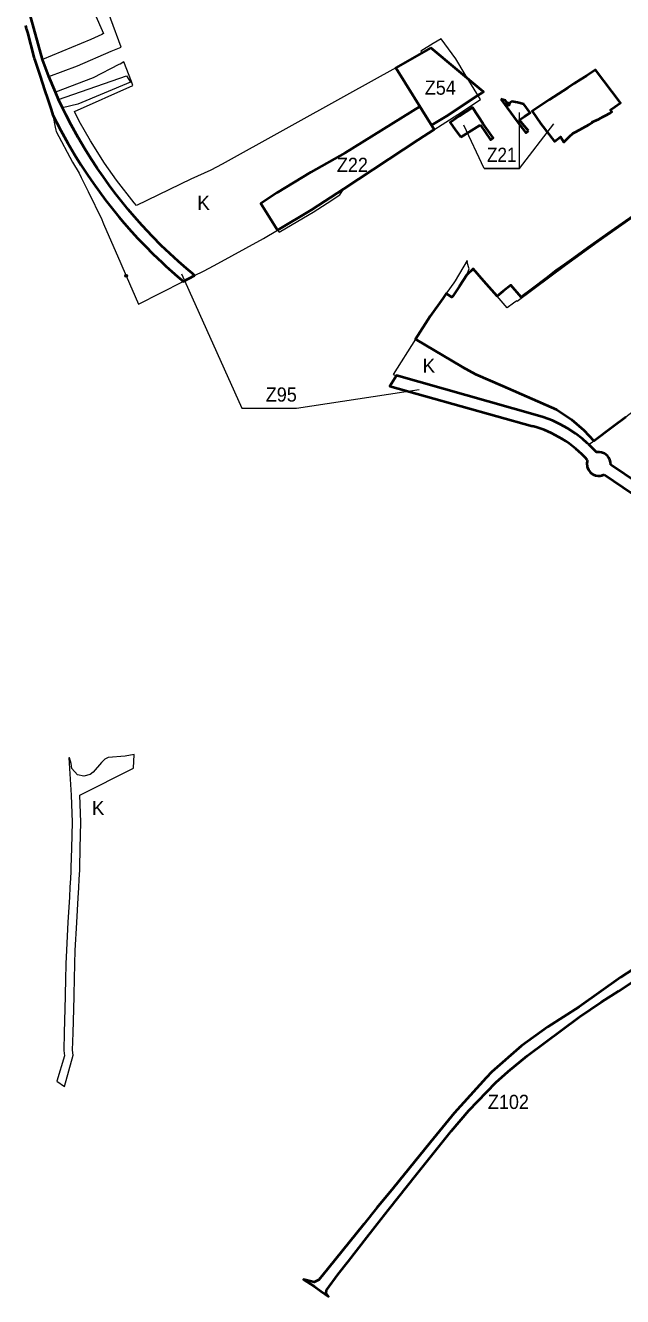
# Model space of a CAD drawing. Extents: x -650276 to -642489, y -1074311 to -1066658.
# Drawn here: x -649054 to -648043, y -1072846 to -1070697 of the extents above; entities that cross this region are included whole.
import ezdxf

# ---------------------------------------------------------------- set-up
doc = ezdxf.new("R2010")
doc.units = 0
doc.header["$LTSCALE"] = 9.6
doc.header["$PDMODE"] = 32
doc.header["$PDSIZE"] = 4.8
for name, color, linetype, lineweight in [('42', 7, 'Continuous', 25), ('44', 7, 'Continuous', 40), ('45', 7, 'Continuous', 40), ('46', 7, 'Continuous', 13), ('47', 7, 'Continuous', 13), ('48', 7, 'Continuous', 13), ('63', 7, 'Continuous', 13)]:
    doc.layers.add(name, color=color, linetype=linetype, lineweight=lineweight)

msp = doc.modelspace()

# ---------------------------------------------------------------- linework, layer by layer
at = {"layer": '42'}
msp.add_lwpolyline([(-648386.587, -1070833.807), (-648512.981, -1070911.776), (-648571.14, -1070944.67), (-648628.712, -1070979.892), (-648655.76, -1070997.5), (-648627.39, -1071042.65), (-648570.23, -1071008.2), (-648515.46, -1070972.94), (-648389.33, -1070889.79), (-648362.519, -1070872.788)], close=True, dxfattribs=at)
at = {"layer": '44'}
for points in [[(-649054.31, -1070696.44), (-649052.77, -1070702.25), (-649052.44, -1070703.48), (-649051.03, -1070708.74), (-649040.03, -1070750.06), (-649039.38, -1070752.51), (-649039.06, -1070753.72), (-649038.51, -1070755.38), (-649027.74, -1070787.51), (-649027.64, -1070787.8), (-649019.48, -1070812.18), (-649018.48, -1070815.18), (-649011.24, -1070836.79), (-649010.67, -1070838.5), (-649007.885, -1070848.153), (-648994.464, -1070873.974), (-648982.467, -1070895.704), (-648970.712, -1070915.663), (-648960.268, -1070932.429), (-648949.389, -1070949.031), (-648939.232, -1070963.818), (-648918.601, -1070991.969), (-648896.068, -1071020.184), (-648886.874, -1071031.044), (-648874.793, -1071044.773), (-648863.847, -1071056.723), (-648851.175, -1071069.886), (-648838.696, -1071082.562), (-648823.087, -1071097.562), (-648816.379, -1071103.782), (-648806.239, -1071112.938), (-648797, -1071121), (-648790.23, -1071126.818), (-648787.207, -1071129.363), (-648767.824, -1071119.455), (-648771.725, -1071116.233), (-648781.806, -1071107.721), (-648795.407, -1071095.8), (-648824.292, -1071068.677), (-648839.273, -1071053.556), (-648856.883, -1071034.761), (-648869.629, -1071020.411), (-648880.44, -1071007.703), (-648894.164, -1070990.806), (-648902.714, -1070979.812), (-648912.396, -1070966.893), (-648922.92, -1070952.242), (-648932.78, -1070937.887), (-648943.414, -1070921.659), (-648953.605, -1070905.299), (-648965.093, -1070885.794), (-648976.834, -1070864.527), (-648985.145, -1070848.538), (-648991.386, -1070835.954), (-648998.132, -1070821.723), (-649003.641, -1070809.566), (-649014.888, -1070782.994), (-649025.129, -1070754.377), (-649047.11, -1070674.743)], [(-648079.109, -1071418.563), (-648082.391, -1071418.063), (-648085.477, -1071418.086), (-648087.928, -1071418.446), (-648100.438, -1071405.517), (-648103.268, -1071402.88), (-648111.646, -1071395.618), (-648123.313, -1071386.696), (-648136.263, -1071378.194), (-648149.571, -1071370.788), (-648162.084, -1071364.918), (-648178.158, -1071358.781), (-648191.25, -1071354.858), (-648426.18, -1071288.32), (-648437.454, -1071306.778), (-648196.236, -1071374.226)], [(-648069.022, -1071424.443), (-648074.341, -1071420.189), (-648079.108, -1071418.564), (-648079.109, -1071418.563)], [(-648063.593, -1071439.723), (-648063.862, -1071435.078), (-648064.838, -1071431.28), (-648066.623, -1071427.592), (-648069.022, -1071424.443)], [(-648103.894, -1071436.836), (-648103.478, -1071442.736), (-648101.203, -1071448.31)], [(-648101.203, -1071448.31), (-648098.259, -1071452.196), (-648096.014, -1071454.192), (-648093.059, -1071456.066), (-648089.539, -1071457.489), (-648085.585, -1071458.248), (-648081.642, -1071458.215), (-648078.539, -1071457.636), (-648074.86, -1071456.248)], [(-648016.446, -1071471.268), (-648063.593, -1071439.723)], [(-648074.86, -1071456.248), (-648027.562, -1071487.894)], [(-647942.21, -1072238.54), (-648046.69, -1072306.3), (-648117.12, -1072356), (-648169.81, -1072390.035), (-648214.73, -1072422.41), (-648264.618, -1072466.244), (-648274.53, -1072476.196), (-648328.847, -1072535.816), (-648369.37, -1072585.645), (-648431.557, -1072662.77), (-648459.243, -1072696.417), (-648481.468, -1072723.736), (-648543.255, -1072800.016), (-648557.588, -1072817.727), (-648565.726, -1072822.048), (-648583.407, -1072817.256), (-648564.86, -1072829.45), (-648554.22, -1072836.89), (-648541.102, -1072846.281), (-648545.462, -1072840.329), (-648544.632, -1072835.177), (-648524.979, -1072808.383), (-648507.503, -1072786.605), (-648476.204, -1072746.1), (-648452.274, -1072715.637), (-648439.912, -1072699.826), (-648391.796, -1072639.344), (-648333.178, -1072565.837), (-648303.791, -1072531.792), (-648258.165, -1072484.283), (-648237.406, -1072465.811), (-648205.298, -1072439.308), (-648116.32, -1072373.44), (-648079.76, -1072348.46), (-648050.276, -1072330.025), (-647969.894, -1072276.479)]]:
    msp.add_lwpolyline(points, dxfattribs=at)
at = {"layer": '44', "lineweight": 13}
msp.add_lwpolyline([(-648790.074, -1071116.496), (-648687.825, -1071343.817), (-648595.588, -1071343.817), (-648387.63, -1071312.498)], dxfattribs=at)
at = {"layer": '44'}
for centre, radius, start, end in [((-648244.965, -1071557.871), 190, 41.59858, 75.1393), ((-648083.781, -1071438.172), 20.157, 161.35794, 176.20098)]:
    msp.add_arc(centre, radius, start, end, dxfattribs=at)
at = {"layer": '45'}
msp.add_lwpolyline([(-648368.163, -1070734.376), (-648427.25, -1070767.95), (-648366.98, -1070865.44), (-648341.58, -1070849.98), (-648287.74, -1070814.32), (-648282.44, -1070810.84), (-648278.832, -1070808.761)], close=True, dxfattribs=at)
for points in [[(-648095.42, -1070860.3), (-648083.65, -1070854.89), (-648076.73, -1070851.07), (-648074.41, -1070849.79), (-648072.59, -1070848.79), (-648065.35, -1070844.8), (-648061.52, -1070842.68), (-648063.76, -1070839.49), (-648056.61, -1070834.26), (-648047.17, -1070827.35), (-648089.27, -1070771.57), (-648104.78, -1070781.65), (-648114.77, -1070788.08), (-648125.2, -1070794.79), (-648136.08, -1070801.79)], [(-648095.42, -1070860.3), (-648083.65, -1070854.89), (-648076.73, -1070851.07), (-648074.41, -1070849.79), (-648072.59, -1070848.79), (-648065.35, -1070844.8), (-648061.52, -1070842.68), (-648063.76, -1070839.49), (-648056.61, -1070834.26), (-648047.17, -1070827.35), (-648089.27, -1070771.57), (-648104.78, -1070781.65), (-648114.77, -1070788.08), (-648125.2, -1070794.79), (-648136.08, -1070801.79)], [(-648136.08, -1070801.79), (-648151.77, -1070812.11), (-648167.6, -1070822.53), (-648196.65, -1070841.7), (-648181.75, -1070862.74), (-648158.58, -1070892.98), (-648148.34, -1070884.92), (-648142.79, -1070893.78), (-648133.14, -1070884.6), (-648127, -1070878.75), (-648122.72, -1070876.44), (-648111.24, -1070870.11), (-648099.85, -1070863.82), (-648094.9, -1070861.09), (-648095.42, -1070860.3)], [(-648136.08, -1070801.79), (-648151.77, -1070812.11), (-648167.6, -1070822.53), (-648196.65, -1070841.7), (-648181.75, -1070862.74), (-648158.58, -1070892.98), (-648148.34, -1070884.92), (-648142.79, -1070893.78), (-648133.14, -1070884.6), (-648127, -1070878.75), (-648122.72, -1070876.44), (-648111.24, -1070870.11), (-648099.85, -1070863.82), (-648094.9, -1070861.09), (-648095.42, -1070860.3)], [(-648237.46, -1070829.68), (-648241.96, -1070823.46), (-648249.5, -1070821.08)], [(-648249.5, -1070821.08), (-648222.158, -1070859.221), (-648217.1, -1070865.56), (-648207.151, -1070878.029), (-648202.798, -1070874.754)], [(-648210.517, -1070829.445), (-648221.58, -1070827.03), (-648231.22, -1070824.92), (-648237.46, -1070829.68)], [(-648386.587, -1070833.807), (-648512.981, -1070911.776), (-648571.14, -1070944.67), (-648628.712, -1070979.892), (-648655.76, -1070997.5), (-648627.39, -1071042.65), (-648570.23, -1071008.2), (-648515.46, -1070972.94), (-648389.33, -1070889.79)], [(-648386.587, -1070833.807), (-648512.981, -1070911.776), (-648571.14, -1070944.67), (-648628.712, -1070979.892), (-648655.76, -1070997.5), (-648627.39, -1071042.65), (-648570.23, -1071008.2), (-648515.46, -1070972.94), (-648389.33, -1070889.79)], [(-648389.33, -1070889.79), (-648362.519, -1070872.788), (-648386.587, -1070833.807)], [(-648389.33, -1070889.79), (-648362.519, -1070872.788), (-648386.587, -1070833.807)], [(-648284.02, -1070864.91), (-648267.24, -1070889.9), (-648262.4, -1070886.58), (-648279.39, -1070862.98), (-648297.39, -1070835.36), (-648320.02, -1070850.16), (-648335.19, -1070860.49), (-648326.41, -1070873.55), (-648317.14, -1070885.48)], [(-648218.11, -1070856.44), (-648209.37, -1070850.44), (-648200.17, -1070844.094), (-648210.517, -1070829.445)], [(-648317.14, -1070885.48), (-648285.72, -1070865.96), (-648284.02, -1070864.91)], [(-648202.798, -1070874.754), (-648212.94, -1070862.74), (-648217.85, -1070856.93), (-648218.11, -1070856.44)], [(-647913.45, -1070940.79), (-648062.53, -1071044.59), (-648102.55, -1071072.86), (-648125.53, -1071089.51), (-648141.12, -1071100.71), (-648155.77, -1071111.23), (-648172.48, -1071123.95), (-648197.57, -1071143.03), (-648215.08, -1071156.35), (-648232.8, -1071135.6), (-648245.49, -1071145.91), (-648256.04, -1071154.5), (-648278.39, -1071128.74), (-648296.34, -1071108.04), (-648307.33, -1071118.47), (-648319.77, -1071137.52), (-648330.78, -1071154.36), (-648332.354, -1071156.279), (-648341.943, -1071150.071), (-648347.949, -1071158.385), (-648369.33, -1071188.149), (-648394.087, -1071227.18), (-648315.127, -1071274.052), (-648292.406, -1071286.112), (-648246.752, -1071306.054), (-648155.113, -1071346.082), (-648130, -1071363), (-648109, -1071381), (-648091.92, -1071399.07), (-648060.01, -1071374.69), (-648038.18, -1071358.51)]]:
    msp.add_lwpolyline(points, dxfattribs=at)
msp.add_point((-648237.46, -1070829.68), dxfattribs=at)
at = {"layer": '46'}
msp.add_line((-648217.945, -1070938.322), (-648217.945, -1070843.952), dxfattribs=at)
for points in [[(-648217.945, -1070938.322), (-648277.841, -1070938.322), (-648311.985, -1070865.23)], [(-648277.841, -1070938.322), (-648217.945, -1070938.322), (-648160.135, -1070863.066)], [(-648217.945, -1070938.322), (-648217.945, -1070938.322), (-648160.135, -1070863.066)]]:
    msp.add_lwpolyline(points, dxfattribs=at)
at = {"layer": '47'}
for p, q in [((-648883.73, -1071120.13), (-648862.97, -1071168.09)), ((-648862.97, -1071168.09), (-648787.207, -1071129.363)), ((-648191.25, -1071354.858), (-648178.158, -1071358.781))]:
    msp.add_line(p, q, dxfattribs=at)
for points in [[(-649014.888, -1070782.994), (-648966.35, -1070764.7), (-648908.94, -1070740.19), (-648892.215, -1070733.293), (-648927.2, -1070637.98), (-648941.064, -1070599.735), (-648965.569, -1070610.382), (-648956.687, -1070630.825), (-649050.081, -1070663.981), (-649047.11, -1070674.743), (-648952.455, -1070640.564), (-648922.196, -1070710.207), (-648924.668, -1070712.022), (-648943.837, -1070720.104), (-649025.129, -1070754.377)], [(-648988.248, -1072491.089), (-648973.238, -1072438.27), (-648974.424, -1072429.462), (-648973.655, -1072400.254), (-648972.605, -1072360.164), (-648972.025, -1072338.183), (-648971.955, -1072335.341), (-648970.605, -1072283.823), (-648970.001, -1072260.788), (-648967.285, -1072213.663), (-648964.865, -1072171.684), (-648963.895, -1072154.905), (-648963.052, -1072140.301), (-648962.27, -1072125.223), (-648962.165, -1072120.949), (-648961.355, -1072088.12), (-648960.263, -1072043.893), (-648962.195, -1071998.309), (-648871.27, -1071952.643), (-648870.458, -1071929.441), (-648885.56, -1071932.1), (-648914.45, -1071934.78), (-648919.79, -1071937.27), (-648925.64, -1071943.18), (-648939.51, -1071959.25), (-648944.69, -1071963.44), (-648955.25, -1071966.15), (-648966.01, -1071963.74), (-648975.65, -1071953.47), (-648976.85, -1071944.78), (-648979.85, -1071935.11), (-648980.94, -1071935.12), (-648977.48, -1071989.2), (-648976.91, -1071998.2), (-648975.27, -1072044.01), (-648976.35, -1072087.75), (-648977.16, -1072120.58), (-648977.26, -1072124.65), (-648977.3, -1072126.08), (-648977.33, -1072127.34), (-648978.03, -1072139.48), (-648978.87, -1072154.04), (-648979.84, -1072170.82), (-648982.26, -1072212.8), (-648984.99, -1072260.16), (-648985.6, -1072283.43), (-648986.31, -1072310.66), (-648986.95, -1072334.96), (-648987.02, -1072337.8), (-648987.6, -1072359.77), (-648988.65, -1072399.86), (-648989.45, -1072430.27), (-648988.27, -1072439.04), (-649000.851, -1072482.138)]]:
    msp.add_lwpolyline(points, close=True, dxfattribs=at)
for points in [[(-648971.041, -1070842.231), (-648872.375, -1070798.112), (-648874.87, -1070791.61), (-648887.84, -1070757.84), (-648894.08, -1070762.22), (-648896.11, -1070762.73), (-648939.5, -1070785.4), (-649003.641, -1070809.566), (-648998.132, -1070821.723), (-648882.919, -1070781.673), (-648876.64, -1070792.6), (-648965.475, -1070829.829), (-648991.386, -1070835.954)], [(-648386.587, -1070833.807), (-648427.25, -1070767.95), (-648511.09, -1070814.7), (-648721.54, -1070930.88), (-648740.25, -1070941.21), (-648774.23, -1070956.42), (-648866.341, -1071000.881)], [(-648991.386, -1070835.954), (-648985.145, -1070848.538), (-648976.834, -1070864.527), (-648965.093, -1070885.794), (-648953.605, -1070905.299), (-648943.414, -1070921.659), (-648932.78, -1070937.887), (-648922.92, -1070952.242), (-648912.396, -1070966.893), (-648902.714, -1070979.812), (-648894.164, -1070990.806), (-648880.44, -1071007.703), (-648869.629, -1071020.411), (-648856.883, -1071034.761), (-648839.273, -1071053.556), (-648824.292, -1071068.677)], [(-648866.341, -1071000.881), (-648870.479, -1070996.265), (-648900.337, -1070957.964), (-648920.293, -1070929.567), (-648944.376, -1070891.404), (-648963.107, -1070858.328), (-648971.041, -1070842.231)], [(-648571.14, -1070944.67), (-648512.981, -1070911.776), (-648386.587, -1070833.807)], [(-648787.207, -1071129.363), (-648790.23, -1071126.818), (-648797, -1071121), (-648806.239, -1071112.938), (-648816.379, -1071103.782), (-648823.087, -1071097.562), (-648838.696, -1071082.562), (-648851.175, -1071069.886), (-648863.847, -1071056.723), (-648874.793, -1071044.773), (-648886.874, -1071031.044), (-648896.068, -1071020.184), (-648918.601, -1070991.969), (-648939.232, -1070963.818), (-648949.389, -1070949.031), (-648960.268, -1070932.429), (-648970.712, -1070915.663), (-648982.467, -1070895.704), (-648994.464, -1070873.974), (-649007.885, -1070848.153), (-649003.1, -1070871.35), (-649002.82, -1070872.69), (-649002.62, -1070873.69), (-649002.15, -1070875.96), (-648974.4, -1070927.77), (-648963.5, -1070946.45), (-648959.92, -1070953.73), (-648948.29, -1070977.37), (-648924.92, -1071024.89), (-648922.98, -1071029.49), (-648921.87, -1071032.04), (-648892.82, -1071099.15), (-648883.73, -1071120.13)], [(-648752.967, -1071111.861), (-648734.849, -1071102.599), (-648651.375, -1071057.109), (-648627.39, -1071042.65), (-648655.76, -1070997.5), (-648634.07, -1070983.17), (-648628.712, -1070979.892), (-648571.153, -1070944.678), (-648571.14, -1070944.67)], [(-648824.292, -1071068.677), (-648795.407, -1071095.8), (-648781.806, -1071107.721), (-648771.725, -1071116.233), (-648767.824, -1071119.455), (-648752.967, -1071111.861)], [(-648130, -1071363), (-648155.113, -1071346.082), (-648246.752, -1071306.054), (-648292.406, -1071286.112), (-648315.127, -1071274.052), (-648394.104, -1071227.17), (-648432.093, -1071286.645), (-648426.18, -1071288.32), (-648191.25, -1071354.858)], [(-648178.158, -1071358.781), (-648178.158, -1071358.781), (-648162.084, -1071364.918)], [(-648136.263, -1071378.194), (-648136.263, -1071378.194), (-648123.313, -1071386.696), (-648111.646, -1071395.618), (-648103.268, -1071402.88), (-648100.438, -1071405.517), (-648091.92, -1071399.07), (-648109, -1071381), (-648130, -1071363)], [(-648162.084, -1071364.918), (-648149.571, -1071370.788), (-648136.263, -1071378.194)]]:
    msp.add_lwpolyline(points, dxfattribs=at)
msp.add_point((-648883.73, -1071120.13), dxfattribs=at)
at = {"layer": '63'}
for points in [[(-648567.23, -1071012.14), (-648543.48, -1070996.94), (-648522.01, -1070983.2), (-648515.46, -1070972.94), (-648389.33, -1070889.79), (-648322.17, -1070847.2), (-648284.021, -1070821.784), (-648309.833, -1070779.597), (-648326.033, -1070753.12), (-648350.805, -1070719.256), (-648363.96, -1070727.29), (-648384.89, -1070740.06)], [(-648384.89, -1070740.06), (-648383.038, -1070743.516), (-648427.25, -1070767.95), (-648386.587, -1070833.807)], [(-648386.587, -1070833.807), (-648472.392, -1070887.048), (-648530.582, -1070922.459), (-648571.14, -1070944.67), (-648634.07, -1070983.17), (-648655.76, -1070997.5), (-648627.39, -1071042.65), (-648625.041, -1071046.388), (-648602.864, -1071033.249), (-648567.23, -1071012.14)], [(-648029.353, -1071023.703), (-648084.716, -1071062.607), (-648140.102, -1071102.285), (-648221.672, -1071163.248), (-648222.669, -1071162.121), (-648228.01, -1071166.19), (-648238.84, -1071174.33), (-648256.04, -1071154.5), (-648278.39, -1071128.74), (-648296.34, -1071108.04), (-648307.33, -1071118.47), (-648303.08, -1071108.16), (-648306.31, -1071097.36), (-648305.83, -1071096.48), (-648306.39, -1071093.99), (-648326.92, -1071128.68), (-648328.9, -1071132.02)], [(-648328.9, -1071132.02), (-648348.051, -1071158.527), (-648369.33, -1071188.149), (-648394.104, -1071227.17), (-648315.127, -1071274.052), (-648292.406, -1071286.112), (-648274.918, -1071293.751), (-648154.21, -1071346.477), (-648154.21, -1071346.477)], [(-648091.92, -1071399.07), (-648074.27, -1071385.62), (-648071.17, -1071383.26), (-648064.98, -1071378.51), (-648060.01, -1071374.69), (-648038.18, -1071358.51), (-648025.39, -1071348.76), (-648009.31, -1071336.48), (-647994.31, -1071325.03), (-647965.26, -1071302.86), (-647954.38, -1071342)], [(-648154.21, -1071346.477), (-648130, -1071363), (-648109, -1071381), (-648091.92, -1071399.07)]]:
    msp.add_lwpolyline(points, dxfattribs=at)

# ---------------------------------------------------------------- texts
at = {"layer": '44', "width": 0.95}
for s, p in [('Z95', (-648647.497, -1071332.741)), ('Z102', (-648271.518, -1072529.04))]:
    msp.add_text(s, height=24, dxfattribs=at).set_placement(p)
at = {"layer": '46'}
for s, width, p in [('Z54', 0.95, (-648378.37, -1070813.706)), ('Z21', 0.9, (-648272.998, -1070927.282)), ('Z22', 0.95, (-648527.125, -1070944.357)), ('Z22', 0.95, (-648527.125, -1070944.357))]:
    msp.add_text(s, height=24, dxfattribs=dict(at, width=width)).set_placement(p)
at = {"layer": '48'}
for p in [(-648763.558, -1071008.525), (-648763.558, -1071008.525), (-648382.039, -1071284.028), (-648941.849, -1072032.089), (-648941.849, -1072032.089)]:
    msp.add_text('K', height=24, dxfattribs=at).set_placement(p)

doc.saveas('drawing.dxf')
